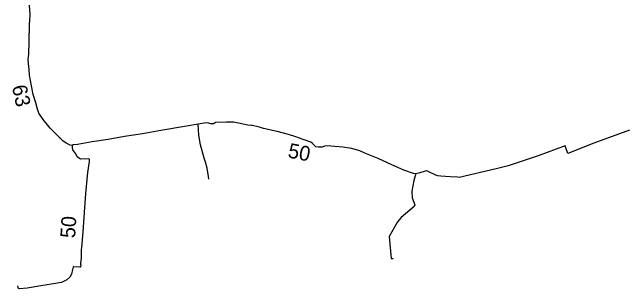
# Model space of a CAD drawing. Extents: x -444817 to -434929, y -1145681 to -1129851.
# Drawn here: x -441637.4 to -441303.1, y -1132645.4 to -1132495.5 of the extents above; entities that cross this region are included whole.
import ezdxf

# ---------------------------------------------------------------- set-up
doc = ezdxf.new("R2010")
doc.units = 0
doc.layers.add('Vrstva 27', color=7, linetype='Continuous')
doc.layers.add('Vrstva 30', color=7, linetype='Continuous')

msp = doc.modelspace()

# ---------------------------------------------------------------- linework, layer by layer
at = {"layer": 'Vrstva 27'}
for points in [[(-441627.98, -1132500), (-441627.72, -1132496.68), (-441628.05, -1132491.82), (-441629.07, -1132488.41), (-441636.47, -1132467.35), (-441636.55, -1132465.87), (-441636.56, -1132463.78), (-441635.95, -1132462.37), (-441635.5, -1132460.35), (-441634.66, -1132459.26), (-441633.58, -1132458.33), (-441629.87, -1132457.28), (-441622.37, -1132455.14), (-441613.69, -1132452.51), (-441605.13, -1132449.68), (-441598.6, -1132447.42), (-441594.3, -1132445.74), (-441591.85, -1132444.58), (-441590.31, -1132443), (-441588.68, -1132440.52), (-441587.35, -1132437.27), (-441587.17, -1132435.1), (-441587.3, -1132433.32)], [(-441611.21, -1132564.13), (-441611.96, -1132563.48), (-441612.28, -1132563.12), (-441616.88, -1132558.35), (-441620.78, -1132553.57), (-441622.97, -1132550.24), (-441623.72, -1132548.03), (-441624.76, -1132544.67), (-441626.04, -1132540.11), (-441627.11, -1132535.34), (-441628.06, -1132529.62), (-441628.21, -1132526.59), (-441628.73, -1132523.26), (-441628.75, -1132520.98), (-441628.46, -1132518.16), (-441628.37, -1132511.55), (-441628.13, -1132502), (-441627.98, -1132500)], [(-441395.47, -1132585.13), (-441396.38, -1132584.88), (-441400.29, -1132584.74), (-441405.45, -1132584.38), (-441407.07, -1132584.12), (-441408.12, -1132583.78), (-441411.82, -1132581.95), (-441413.01, -1132581.55), (-441413.79, -1132581.69), (-441417.35, -1132582.65), (-441419.28, -1132583.1), (-441420.24, -1132582.97), (-441425.36, -1132581.09), (-441431.86, -1132578.27), (-441439.36, -1132574.81), (-441446.46, -1132571.83), (-441449.31, -1132570.62), (-441453.56, -1132569.44), (-441457.38, -1132568.8), (-441458.41, -1132568.71), (-441460.4, -1132568.55), (-441467.27, -1132567.97), (-441468.34, -1132568.18), (-441469.71, -1132568.58), (-441471.62, -1132568.68), (-441473.01, -1132568.41), (-441474.92, -1132566.63), (-441475.78, -1132565.97), (-441479.88, -1132564.4), (-441483.94, -1132563.04), (-441487.89, -1132561.71), (-441494.04, -1132560.19), (-441501.32, -1132558.55), (-441502.97, -1132557.97), (-441504.28, -1132557.56), (-441507.3, -1132556.93), (-441507.85, -1132556.87), (-441509.88, -1132556.67), (-441514.93, -1132555.57), (-441517.63, -1132555.1), (-441521.46, -1132555.08), (-441527.34, -1132555.2), (-441528.38, -1132555.93), (-441529.96, -1132555.99), (-441531.76, -1132555.53), (-441533.45, -1132555.64), (-441536.8, -1132556.15), (-441543.04, -1132557.24), (-441556.96, -1132559.64), (-441566.97, -1132561.39), (-441576.68, -1132562.87), (-441585.47, -1132564.48), (-441594.2, -1132565.83), (-441602.04, -1132567.12), (-441604.61, -1132567.4), (-441604.86, -1132567.77)], [(-441530.92, -1132586.04), (-441531.15, -1132584.51), (-441531.94, -1132580.11), (-441532.78, -1132576.71), (-441533.53, -1132574.52), (-441535.56, -1132567.3), (-441536.38, -1132562.08), (-441536.79, -1132556.43), (-441536.8, -1132556.15)], [(-441303.12, -1132559.41), (-441322.45, -1132566.42), (-441336.67, -1132572.03), (-441338.05, -1132567.89)], [(-441604.86, -1132567.77), (-441606.13, -1132567.51), (-441608.18, -1132566.55), (-441610.15, -1132565.12), (-441611.21, -1132564.13)], [(-441600.36, -1132632.53), (-441600.28, -1132631.78), (-441599.95, -1132628.61), (-441599.91, -1132624.1), (-441599.73, -1132623.09), (-441599.05, -1132614.61), (-441598.25, -1132604.15), (-441597.56, -1132593.84), (-441596.55, -1132582.41), (-441595.68, -1132576.45), (-441595.64, -1132575.4), (-441596.07, -1132575.03), (-441600.24, -1132575.06), (-441601.01, -1132574.84), (-441602.38, -1132573.83), (-441603.11, -1132572.17), (-441604.04, -1132570.75), (-441604.69, -1132570.04), (-441604.91, -1132568.84), (-441604.86, -1132567.77)], [(-441338.05, -1132567.89), (-441352.65, -1132573.42), (-441368.83, -1132578.81), (-441375.42, -1132580.44), (-441395.47, -1132585.13)], [(-441418.89, -1132583.01), (-441420.07, -1132586.64), (-441421.1, -1132592.48), (-441420.94, -1132596.03), (-441419.42, -1132599.94), (-441419.82, -1132600.9), (-441426.86, -1132606.73), (-441428.85, -1132609.07), (-441433.26, -1132617.17), (-441432.35, -1132628.99), (-441431.11, -1132629.1)], [(-441600.36, -1132632.53), (-441600.57, -1132633.64), (-441600.73, -1132633.78), (-441600.92, -1132633.76), (-441604.18, -1132633.5), (-441604.47, -1132633.59), (-441604.76, -1132635.03), (-441605.41, -1132637.46), (-441606.29, -1132639.06), (-441607.91, -1132640.53), (-441610.74, -1132642.07), (-441613.99, -1132642.6), (-441621.95, -1132643.77), (-441629.38, -1132645.08), (-441633.57, -1132645.37), (-441634.09, -1132645.22), (-441634.32, -1132644.78), (-441634.4, -1132643.84)]]:
    msp.add_lwpolyline(points, dxfattribs=at)

# ---------------------------------------------------------------- texts
at = {"layer": 'Vrstva 30'}
for s, rotation, p in [('63', 282.6432, (-441637.7, -1132535.76)), ('50', 349.0075, (-441488.58, -1132574.18)), ('50', 86.1767, (-441603.49, -1132618.15))]:
    msp.add_text(s, height=8, rotation=rotation, dxfattribs=at).set_placement(p)

doc.saveas('drawing.dxf')
